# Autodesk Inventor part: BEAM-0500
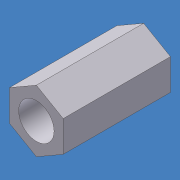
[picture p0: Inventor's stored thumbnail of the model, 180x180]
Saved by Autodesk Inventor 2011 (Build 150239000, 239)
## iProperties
Created: 2007-10
Part Number: BEAM-0500
Document SubType Name: Modeling
Material: Aluminum-6061
Density: 2.71 g/cm^3
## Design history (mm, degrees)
feature "Base1"
body "Solid1"
